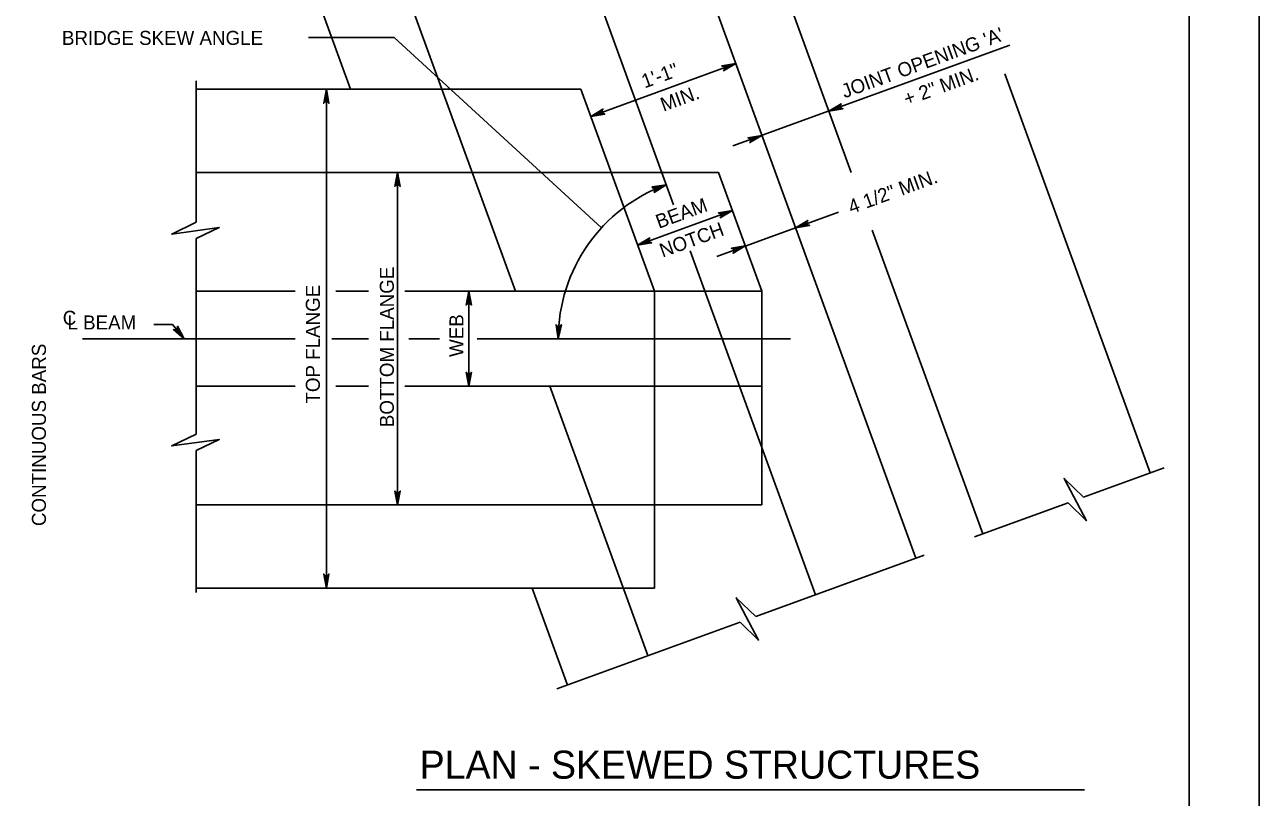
# Model space of a CAD drawing. Extents: x 638653 to 642302, y 298557 to 300414.
# Drawn here: x 641241.1 to 641505.2, y 299443.5 to 299608.7 of the extents above; entities that cross this region are included whole.
import ezdxf

# ---------------------------------------------------------------- set-up
doc = ezdxf.new("R2010")
doc.units = 0
doc.layers.add('1', color=7, linetype='Continuous')
doc.layers.add('PLT-BNDY', color=7, linetype='Continuous')

msp = doc.modelspace()

# ---------------------------------------------------------------- linework, layer by layer
at = {"layer": '1'}
for p, q in [((641490.16, 299729.52), (641490.16, 299165.52)), ((641431.68, 299494.65), (641373.14, 299655.48)), ((641346.02, 299551.74), (641315.85, 299634.63)), ((641310.77, 299594.92), (641298.6, 299628.35)), ((641379.83, 299570.24), (641358.97, 299627.57)), ((641417.87, 299577.15), (641401.89, 299621.03)), ((641301.77, 299605.99), (641320.06, 299605.99)), ((641320.06, 299605.99), (641364.44, 299565.28)), ((641392.57, 299582.8), (641451.79, 299604.35)), ((641362.15, 299589.13), (641393.18, 299600.42)), ((641481.8, 299512.89), (641450.74, 299598.22)), ((641277.72, 299596.72), (641277.72, 299566.5)), ((641277.72, 299594.92), (641360.04, 299594.92)), ((641305.59, 299594.92), (641305.59, 299488.24)), ((641375.76, 299551.74), (641360.04, 299594.92)), ((641277.72, 299577.15), (641366.51, 299577.15)), ((641320.83, 299577.15), (641320.83, 299506.02)), ((641366.51, 299577.15), (641389.49, 299577.15)), ((641398.73, 299551.74), (641389.49, 299577.15)), ((641372.17, 299561.59), (641392.46, 299568.97)), ((641389.11, 299559.19), (641415.13, 299568.66)), ((641446, 299499.86), (641422.36, 299564.81)), ((641277.72, 299562.98), (641277.72, 299521.18)), ((641410.19, 299486.83), (641383.42, 299560.4)), ((641277.72, 299551.74), (641298.93, 299551.74)), ((641307.62, 299551.74), (641314.57, 299551.74)), ((641322.39, 299551.74), (641375.76, 299551.74)), ((641336.07, 299551.74), (641336.07, 299531.43)), ((641375.76, 299488.24), (641375.76, 299551.74)), ((641375.76, 299551.74), (641398.73, 299551.74)), ((641398.73, 299506.02), (641398.73, 299551.74)), ((641268.72, 299544.61), (641272.71, 299544.61)), ((641272.71, 299544.61), (641275.18, 299541.58)), ((641253.42, 299541.58), (641298.93, 299541.58)), ((641306.75, 299541.58), (641314.57, 299541.58)), ((641323.26, 299541.58), (641329.77, 299541.58)), ((641337.83, 299541.58), (641404.88, 299541.58)), ((641277.72, 299531.43), (641298.93, 299531.43)), ((641307.62, 299531.43), (641314.57, 299531.43)), ((641322.39, 299531.43), (641375.76, 299531.43)), ((641374.39, 299473.8), (641353.42, 299531.43)), ((641375.76, 299531.43), (641398.73, 299531.43)), ((641277.72, 299517.66), (641277.72, 299487.34)), ((641484.81, 299513.99), (641467.56, 299507.71)), ((641277.72, 299506.02), (641375.76, 299506.02)), ((641375.76, 299506.02), (641398.73, 299506.02)), ((641464.26, 299506.51), (641444.25, 299499.22)), ((641433.46, 299495.3), (641397.44, 299482.19)), ((641277.72, 299488.24), (641375.76, 299488.24)), ((641357.14, 299467.52), (641349.6, 299488.24)), ((641394.13, 299480.98), (641354.9, 299466.7)), ((641324.86, 299445.08), (641467.75, 299445.08))]:
    msp.add_line(p, q, dxfattribs=at)
for points in [[(641393.18, 299600.42), (641390.56, 299598.88), (641390.65, 299598.99), (641390.73, 299599.11), (641390.75, 299599.22), (641390.77, 299599.33), (641390.75, 299599.43), (641390.73, 299599.53), (641390.68, 299599.62), (641390.63, 299599.71), (641390.54, 299599.78), (641390.45, 299599.86), (641390.32, 299599.89), (641390.18, 299599.93), (641393.18, 299600.42), (641390.32, 299599.89), (641390.45, 299599.86), (641393.18, 299600.42), (641390.54, 299599.78), (641390.63, 299599.71), (641393.18, 299600.42), (641390.68, 299599.62), (641390.73, 299599.53), (641393.18, 299600.42), (641390.75, 299599.43), (641390.77, 299599.33), (641393.18, 299600.42), (641390.75, 299599.22), (641390.73, 299599.11), (641393.18, 299600.42), (641390.65, 299598.99)], [(641305.59, 299594.92), (641306.15, 299591.94), (641306.07, 299592.06), (641305.99, 299592.17), (641305.89, 299592.23), (641305.79, 299592.29), (641305.69, 299592.31), (641305.59, 299592.32), (641305.49, 299592.31), (641305.39, 299592.29), (641305.29, 299592.23), (641305.19, 299592.17), (641305.11, 299592.06), (641305.03, 299591.94), (641305.59, 299594.92), (641305.11, 299592.06), (641305.19, 299592.17), (641305.59, 299594.92), (641305.29, 299592.23), (641305.39, 299592.29), (641305.59, 299594.92), (641305.49, 299592.31), (641305.59, 299592.32), (641305.59, 299594.92), (641305.69, 299592.31), (641305.79, 299592.29), (641305.59, 299594.92), (641305.89, 299592.23), (641305.99, 299592.17), (641305.59, 299594.92), (641306.07, 299592.06)], [(641362.15, 299589.13), (641364.76, 299590.68), (641364.68, 299590.56), (641364.6, 299590.45), (641364.58, 299590.33), (641364.56, 299590.22), (641364.57, 299590.12), (641364.59, 299590.02), (641364.64, 299589.93), (641364.69, 299589.84), (641364.78, 299589.77), (641364.87, 299589.7), (641365.01, 299589.66), (641365.14, 299589.62), (641362.15, 299589.13), (641365.01, 299589.66), (641364.87, 299589.7), (641362.15, 299589.13), (641364.78, 299589.77), (641364.69, 299589.84), (641362.15, 299589.13), (641364.64, 299589.93), (641364.59, 299590.02), (641362.15, 299589.13), (641364.57, 299590.12), (641364.56, 299590.22), (641362.15, 299589.13), (641364.58, 299590.33), (641364.6, 299590.45), (641362.15, 299589.13), (641364.68, 299590.56)], [(641413.09, 299590.27), (641415.7, 299591.81), (641415.62, 299591.7), (641415.54, 299591.59), (641415.52, 299591.47), (641415.5, 299591.36), (641415.52, 299591.26), (641415.53, 299591.16), (641415.58, 299591.07), (641415.63, 299590.98), (641415.72, 299590.91), (641415.81, 299590.83), (641415.95, 299590.8), (641416.08, 299590.76), (641413.09, 299590.27), (641415.95, 299590.8), (641415.81, 299590.83), (641413.09, 299590.27), (641415.72, 299590.91), (641415.63, 299590.98), (641413.09, 299590.27), (641415.58, 299591.07), (641415.53, 299591.16), (641413.09, 299590.27), (641415.52, 299591.26), (641415.5, 299591.36), (641413.09, 299590.27), (641415.52, 299591.47), (641415.54, 299591.59), (641413.09, 299590.27), (641415.62, 299591.7)], [(641398.77, 299585.06), (641396.16, 299583.51), (641396.24, 299583.63), (641396.32, 299583.74), (641396.34, 299583.85), (641396.36, 299583.97), (641396.34, 299584.07), (641396.33, 299584.17), (641396.28, 299584.26), (641396.23, 299584.34), (641396.14, 299584.42), (641396.05, 299584.49), (641395.91, 299584.53), (641395.78, 299584.56), (641398.77, 299585.06), (641395.91, 299584.53), (641396.05, 299584.49), (641398.77, 299585.06), (641396.14, 299584.42), (641396.23, 299584.34), (641398.77, 299585.06), (641396.28, 299584.26), (641396.33, 299584.17), (641398.77, 299585.06), (641396.34, 299584.07), (641396.36, 299583.97), (641398.77, 299585.06), (641396.34, 299583.85), (641396.32, 299583.74), (641398.77, 299585.06), (641396.24, 299583.63)], [(641320.83, 299577.15), (641321.39, 299574.16), (641321.31, 299574.28), (641321.23, 299574.39), (641321.13, 299574.45), (641321.03, 299574.51), (641320.93, 299574.53), (641320.83, 299574.55), (641320.73, 299574.53), (641320.63, 299574.51), (641320.53, 299574.45), (641320.43, 299574.39), (641320.35, 299574.28), (641320.27, 299574.16), (641320.83, 299577.15), (641320.35, 299574.28), (641320.43, 299574.39), (641320.83, 299577.15), (641320.53, 299574.45), (641320.63, 299574.51), (641320.83, 299577.15), (641320.73, 299574.53), (641320.83, 299574.55), (641320.83, 299577.15), (641320.93, 299574.53), (641321.03, 299574.51), (641320.83, 299577.15), (641321.13, 299574.45), (641321.23, 299574.39), (641320.83, 299577.15), (641321.31, 299574.28)], [(641378.28, 299574.52), (641375.66, 299572.98), (641375.75, 299573.09), (641375.83, 299573.21), (641375.85, 299573.32), (641375.87, 299573.43), (641375.85, 299573.53), (641375.83, 299573.63), (641375.78, 299573.72), (641375.73, 299573.81), (641375.64, 299573.88), (641375.55, 299573.96), (641375.42, 299573.99), (641375.28, 299574.03), (641378.28, 299574.52), (641375.42, 299573.99), (641375.55, 299573.96), (641378.28, 299574.52), (641375.64, 299573.88), (641375.73, 299573.81), (641378.28, 299574.52), (641375.78, 299573.72), (641375.83, 299573.63), (641378.28, 299574.52), (641375.85, 299573.53), (641375.87, 299573.43), (641378.28, 299574.52), (641375.85, 299573.32), (641375.83, 299573.21), (641378.28, 299574.52), (641375.75, 299573.09)], [(641378.28, 299574.52), (641375.73, 299572.87), (641375.81, 299572.99), (641375.88, 299573.11), (641375.9, 299573.22), (641375.92, 299573.34), (641375.89, 299573.43), (641375.87, 299573.53), (641375.82, 299573.62), (641375.76, 299573.71), (641375.67, 299573.78), (641375.58, 299573.84), (641375.44, 299573.87), (641375.31, 299573.9), (641378.28, 299574.52), (641375.44, 299573.87), (641375.58, 299573.84), (641378.28, 299574.52), (641375.67, 299573.78), (641375.76, 299573.71), (641378.28, 299574.52), (641375.82, 299573.62), (641375.87, 299573.53), (641378.28, 299574.52), (641375.89, 299573.43), (641375.92, 299573.34), (641378.28, 299574.52), (641375.9, 299573.22), (641375.88, 299573.11), (641378.28, 299574.52), (641375.81, 299572.99)], [(641392.46, 299568.97), (641389.85, 299567.43), (641389.93, 299567.54), (641390.01, 299567.66), (641390.03, 299567.77), (641390.05, 299567.88), (641390.03, 299567.98), (641390.02, 299568.08), (641389.97, 299568.17), (641389.92, 299568.26), (641389.83, 299568.33), (641389.74, 299568.41), (641389.6, 299568.44), (641389.47, 299568.48), (641392.46, 299568.97), (641389.6, 299568.44), (641389.74, 299568.41), (641392.46, 299568.97), (641389.83, 299568.33), (641389.92, 299568.26), (641392.46, 299568.97), (641389.97, 299568.17), (641390.02, 299568.08), (641392.46, 299568.97), (641390.03, 299567.98), (641390.05, 299567.88), (641392.46, 299568.97), (641390.03, 299567.77), (641390.01, 299567.66), (641392.46, 299568.97), (641389.93, 299567.54)], [(641277.72, 299566.5), (641272.53, 299563.96), (641282.68, 299565.34), (641277.72, 299562.98)], [(641405.95, 299565.32), (641408.56, 299566.87), (641408.48, 299566.75), (641408.4, 299566.64), (641408.38, 299566.52), (641408.36, 299566.41), (641408.38, 299566.31), (641408.4, 299566.21), (641408.45, 299566.12), (641408.5, 299566.03), (641408.59, 299565.96), (641408.68, 299565.89), (641408.81, 299565.85), (641408.95, 299565.81), (641405.95, 299565.32), (641408.81, 299565.85), (641408.68, 299565.89), (641405.95, 299565.32), (641408.59, 299565.96), (641408.5, 299566.03), (641405.95, 299565.32), (641408.45, 299566.12), (641408.4, 299566.21), (641405.95, 299565.32), (641408.38, 299566.31), (641408.36, 299566.41), (641405.95, 299565.32), (641408.38, 299566.52), (641408.4, 299566.64), (641405.95, 299565.32), (641408.48, 299566.75)], [(641372.17, 299561.59), (641374.78, 299563.13), (641374.7, 299563.02), (641374.62, 299562.91), (641374.6, 299562.79), (641374.58, 299562.68), (641374.6, 299562.58), (641374.62, 299562.48), (641374.67, 299562.39), (641374.72, 299562.3), (641374.81, 299562.23), (641374.9, 299562.15), (641375.03, 299562.12), (641375.17, 299562.08), (641372.17, 299561.59), (641375.03, 299562.12), (641374.9, 299562.15), (641372.17, 299561.59), (641374.81, 299562.23), (641374.72, 299562.3), (641372.17, 299561.59), (641374.67, 299562.39), (641374.62, 299562.48), (641372.17, 299561.59), (641374.6, 299562.58), (641374.58, 299562.68), (641372.17, 299561.59), (641374.6, 299562.79), (641374.62, 299562.91), (641372.17, 299561.59), (641374.7, 299563.02)], [(641395.21, 299561.41), (641392.6, 299559.86), (641392.68, 299559.98), (641392.76, 299560.09), (641392.78, 299560.21), (641392.81, 299560.32), (641392.79, 299560.42), (641392.77, 299560.52), (641392.72, 299560.61), (641392.67, 299560.7), (641392.58, 299560.77), (641392.49, 299560.84), (641392.35, 299560.88), (641392.22, 299560.92), (641395.21, 299561.41), (641392.35, 299560.88), (641392.49, 299560.84), (641395.21, 299561.41), (641392.58, 299560.77), (641392.67, 299560.7), (641395.21, 299561.41), (641392.72, 299560.61), (641392.77, 299560.52), (641395.21, 299561.41), (641392.79, 299560.42), (641392.81, 299560.32), (641395.21, 299561.41), (641392.78, 299560.21), (641392.76, 299560.09), (641395.21, 299561.41), (641392.68, 299559.98)], [(641336.07, 299551.74), (641336.63, 299548.76), (641336.55, 299548.88), (641336.47, 299548.99), (641336.37, 299549.05), (641336.27, 299549.11), (641336.17, 299549.13), (641336.07, 299549.14), (641335.97, 299549.13), (641335.87, 299549.11), (641335.77, 299549.05), (641335.67, 299548.99), (641335.59, 299548.88), (641335.51, 299548.76), (641336.07, 299551.74), (641335.59, 299548.88), (641335.67, 299548.99), (641336.07, 299551.74), (641335.77, 299549.05), (641335.87, 299549.11), (641336.07, 299551.74), (641335.97, 299549.13), (641336.07, 299549.14), (641336.07, 299551.74), (641336.17, 299549.13), (641336.27, 299549.11), (641336.07, 299551.74), (641336.37, 299549.05), (641336.47, 299548.99), (641336.07, 299551.74), (641336.55, 299548.88)], [(641275.18, 299541.58), (641272.86, 299543.54), (641273, 299543.5), (641273.13, 299543.46), (641273.25, 299543.48), (641273.36, 299543.5), (641273.45, 299543.55), (641273.54, 299543.6), (641273.6, 299543.67), (641273.67, 299543.75), (641273.71, 299543.86), (641273.75, 299543.97), (641273.74, 299544.11), (641273.73, 299544.25), (641275.18, 299541.58), (641273.74, 299544.11), (641273.75, 299543.97), (641275.18, 299541.58), (641273.71, 299543.86), (641273.67, 299543.75), (641275.18, 299541.58), (641273.6, 299543.67), (641273.54, 299543.6), (641275.18, 299541.58), (641273.45, 299543.55), (641273.36, 299543.5), (641275.18, 299541.58), (641273.25, 299543.48), (641273.13, 299543.46), (641275.18, 299541.58), (641273, 299543.5)], [(641355.21, 299541.58), (641354.74, 299544.58), (641354.82, 299544.47), (641354.89, 299544.35), (641354.99, 299544.29), (641355.09, 299544.22), (641355.19, 299544.2), (641355.29, 299544.18), (641355.39, 299544.2), (641355.49, 299544.21), (641355.59, 299544.27), (641355.69, 299544.32), (641355.78, 299544.44), (641355.86, 299544.55), (641355.21, 299541.58), (641355.78, 299544.44), (641355.69, 299544.32), (641355.21, 299541.58), (641355.59, 299544.27), (641355.49, 299544.21), (641355.21, 299541.58), (641355.39, 299544.2), (641355.29, 299544.18), (641355.21, 299541.58), (641355.19, 299544.2), (641355.09, 299544.22), (641355.21, 299541.58), (641354.99, 299544.29), (641354.89, 299544.35), (641355.21, 299541.58), (641354.82, 299544.47)], [(641336.07, 299531.43), (641335.51, 299534.41), (641335.59, 299534.29), (641335.67, 299534.18), (641335.77, 299534.12), (641335.87, 299534.06), (641335.97, 299534.04), (641336.07, 299534.03), (641336.17, 299534.04), (641336.27, 299534.06), (641336.37, 299534.12), (641336.47, 299534.18), (641336.55, 299534.29), (641336.63, 299534.41), (641336.07, 299531.43), (641336.55, 299534.29), (641336.47, 299534.18), (641336.07, 299531.43), (641336.37, 299534.12), (641336.27, 299534.06), (641336.07, 299531.43), (641336.17, 299534.04), (641336.07, 299534.03), (641336.07, 299531.43), (641335.97, 299534.04), (641335.87, 299534.06), (641336.07, 299531.43), (641335.77, 299534.12), (641335.67, 299534.18), (641336.07, 299531.43), (641335.59, 299534.29)], [(641277.72, 299521.18), (641272.53, 299518.64), (641282.68, 299520.02), (641277.72, 299517.66)], [(641467.56, 299507.71), (641463.41, 299511.71), (641468.17, 299502.65), (641464.26, 299506.51)], [(641320.83, 299506.02), (641320.27, 299509.01), (641320.35, 299508.89), (641320.43, 299508.78), (641320.53, 299508.72), (641320.63, 299508.66), (641320.73, 299508.64), (641320.83, 299508.62), (641320.93, 299508.64), (641321.03, 299508.66), (641321.13, 299508.72), (641321.23, 299508.78), (641321.31, 299508.89), (641321.39, 299509.01), (641320.83, 299506.02), (641321.31, 299508.89), (641321.23, 299508.78), (641320.83, 299506.02), (641321.13, 299508.72), (641321.03, 299508.66), (641320.83, 299506.02), (641320.93, 299508.64), (641320.83, 299508.62), (641320.83, 299506.02), (641320.73, 299508.64), (641320.63, 299508.66), (641320.83, 299506.02), (641320.53, 299508.72), (641320.43, 299508.78), (641320.83, 299506.02), (641320.35, 299508.89)], [(641305.59, 299488.24), (641305.03, 299491.23), (641305.11, 299491.11), (641305.19, 299491), (641305.29, 299490.94), (641305.39, 299490.88), (641305.49, 299490.86), (641305.59, 299490.84), (641305.69, 299490.86), (641305.79, 299490.88), (641305.89, 299490.94), (641305.99, 299491), (641306.07, 299491.11), (641306.15, 299491.23), (641305.59, 299488.24), (641306.07, 299491.11), (641305.99, 299491), (641305.59, 299488.24), (641305.89, 299490.94), (641305.79, 299490.88), (641305.59, 299488.24), (641305.69, 299490.86), (641305.59, 299490.84), (641305.59, 299488.24), (641305.49, 299490.86), (641305.39, 299490.88), (641305.59, 299488.24), (641305.29, 299490.94), (641305.19, 299491), (641305.59, 299488.24), (641305.11, 299491.11)], [(641397.44, 299482.19), (641393.28, 299486.19), (641398.05, 299477.13), (641394.13, 299480.98)]]:
    msp.add_lwpolyline(points, dxfattribs=at)
msp.add_arc((641390.26, 299541.58), 35.05, 110, 180, dxfattribs=at)
at = {"layer": 'PLT-BNDY'}
msp.add_lwpolyline([(640664.16, 299744.52), (641505.16, 299744.52), (641505.16, 299150.52), (640664.16, 299150.52)], close=True, dxfattribs=at)

# ---------------------------------------------------------------- texts
at = {"layer": '1'}
for s, height, p in [('BRIDGE SKEW ANGLE', 3, (641249.03, 299604.41)), ('C', 3, (641249.2, 299544.55)), ('L BEAM', 3, (641250.21, 299543.55)), ('PLAN - SKEWED STRUCTURES', 6, (641325.55, 299447.49))]:
    msp.add_text(s, height=height, dxfattribs=at).set_placement(p)
for s, rotation, p in [("JOINT OPENING 'A'", 20, (641416.44, 299592.96)), ('1\'-1"', 20, (641373.67, 299595.09)), ('+ 2" MIN.', 20, (641429.73, 299591.33)), ('MIN.', 20, (641377.72, 299590.1)), ('4 1/2" MIN.', 20, (641417.89, 299568.23)), ('BEAM', 20, (641376.71, 299565.07)), ('NOTCH', 20, (641377.52, 299558.9)), ('BOTTOM FLANGE', 90, (641320.03, 299522.66)), ('TOP FLANGE', 90, (641304.2, 299527.71)), ('WEB', 90, (641334.92, 299537.68)), ('CONTINUOUS BARS', 90, (641245.6, 299501.51))]:
    msp.add_text(s, height=3, rotation=rotation, dxfattribs=at).set_placement(p)

doc.saveas('drawing.dxf')
